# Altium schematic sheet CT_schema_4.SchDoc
size 287 x 163 mm
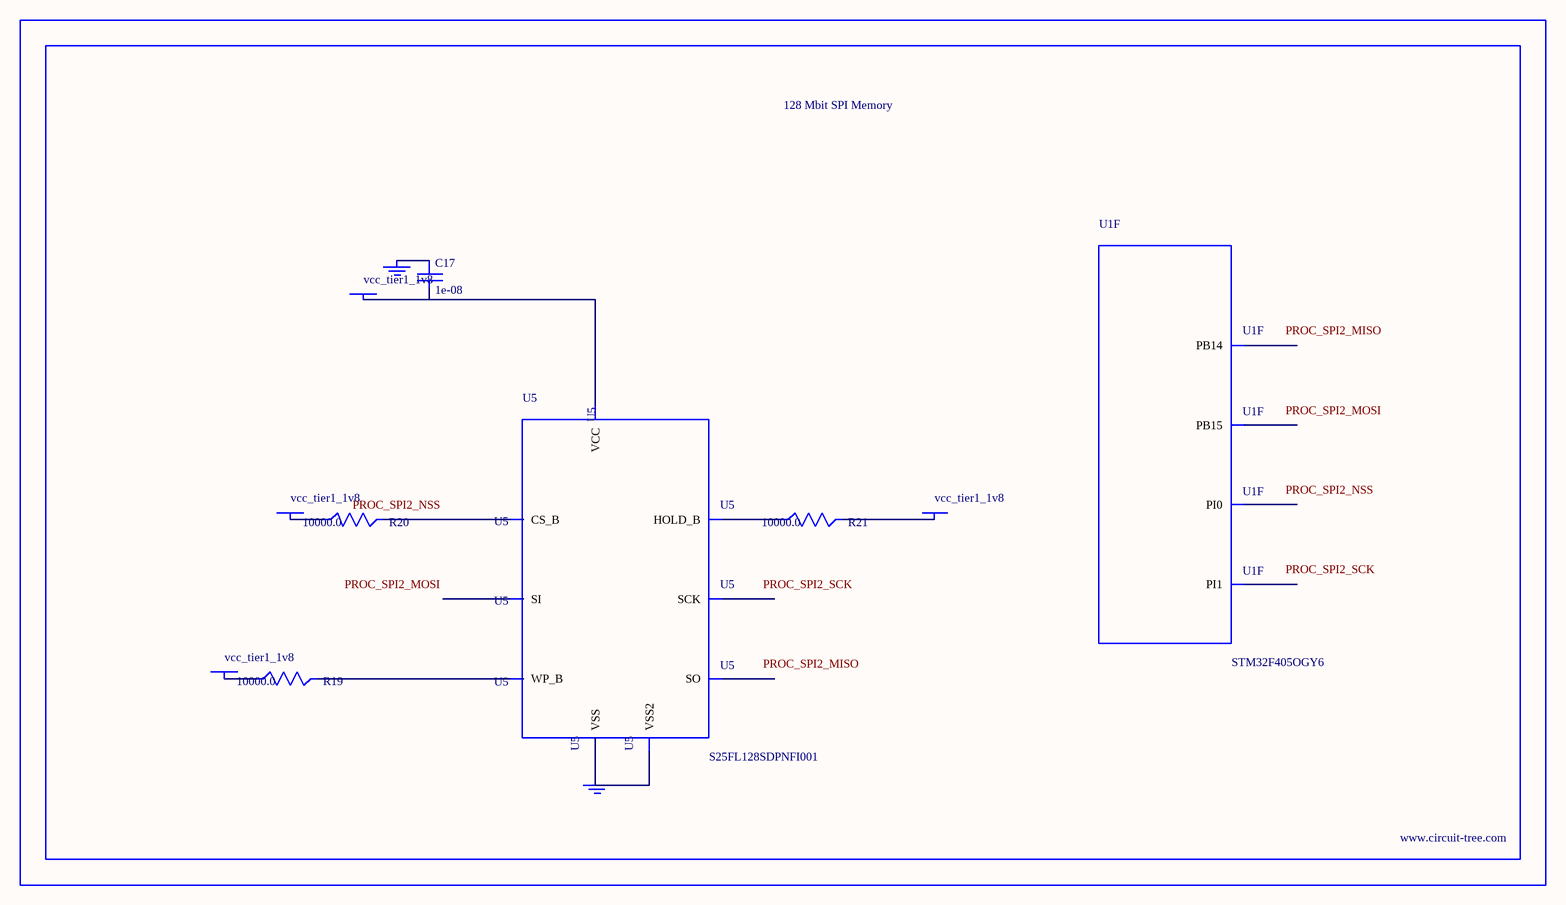
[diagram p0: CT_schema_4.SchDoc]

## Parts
BORDER3  (no value)
C17  1e-08  [C0402]
GND_INSTANCE_3_0  (no value)
GND_INSTANCE_3_1  (no value)
POWER_INSTANCE_3_0  vcc_tier1_1v8
POWER_INSTANCE_3_1  vcc_tier1_1v8
POWER_INSTANCE_3_2  vcc_tier1_1v8
POWER_INSTANCE_3_3  vcc_tier1_1v8
R19  10000.0  [R0603]
R20  10000.0  [R0603]
R21  10000.0  [R0603]
U1  STM32F405OGY6  [WLCSP90]  (part F of 9)
U5  S25FL128SDPNFI001  [WNG008]

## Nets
NetC17_1: C17.1 GND_INSTANCE_3_0.0(GND)
NetC17_2: C17.2 POWER_INSTANCE_3_3.0(PWR) U5.8(VCC)
NetGND_INSTANCE_3_1_0: GND_INSTANCE_3_1.0(GND) U5.4(VSS) U5.PAD(VSS2)
NetPOWER_INSTANCE_3_0_0: POWER_INSTANCE_3_0.0(PWR) R20.1
NetPOWER_INSTANCE_3_1_0: POWER_INSTANCE_3_1.0(PWR) R19.1
NetPOWER_INSTANCE_3_2_0: POWER_INSTANCE_3_2.0(PWR) R21.2
NetR19_2: R19.2 U5.3(WP_B)
NetR20_2: R20.2 U5.1(CS_B)
NetR21_1: R21.1 U5.7(HOLD_B)

Not connected (* = marked no-connect by the designer): U1 B2(PI1) C3(PI0) H1(PB15) J2(PB14); U5 2(SO) 5(SI) 6(SCK)

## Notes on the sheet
- Labels drawn without touching a wire or pin: PROC_SPI2_MISO, PROC_SPI2_MOSI, PROC_SPI2_NSS, PROC_SPI2_SCK

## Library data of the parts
BORDER3 = BORDER_PAGE3
C17 = C0402C103K3RAC
GND_INSTANCE_3_0 GND_INSTANCE_3_1 = GND
POWER_INSTANCE_3_0-POWER_INSTANCE_3_3 = PWR
R19-R21 = RC0603JR-0710KL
